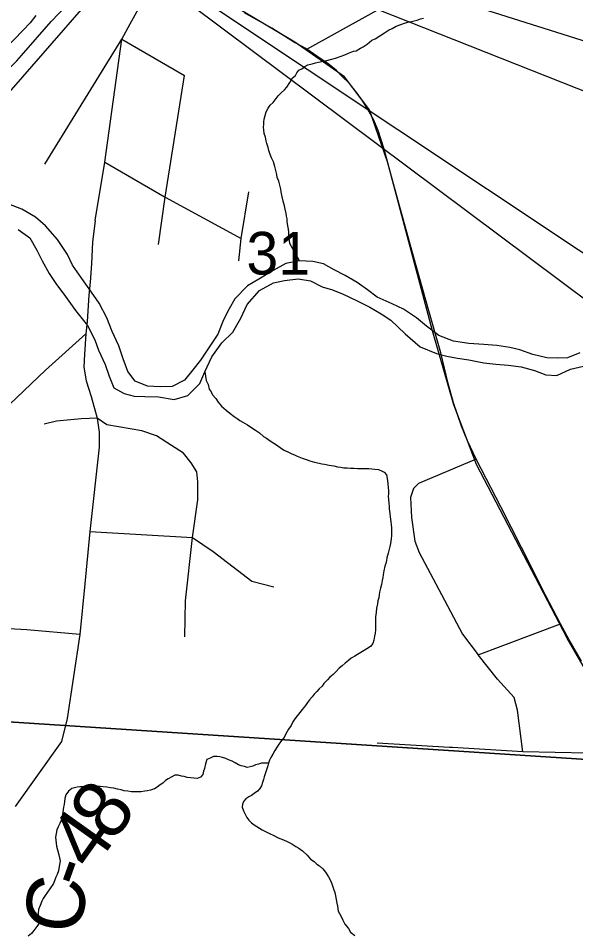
# Model space of a CAD drawing. Extents: x -7.3 to 34, y 0 to 22.
# Drawn here: x 5.85 to 6.397, y 16.795 to 17.693 of the extents above; entities that cross this region are included whole.
import ezdxf

# ---------------------------------------------------------------- set-up
doc = ezdxf.new("R2010")
doc.units = 0
for name, color, linetype in [('GM_X_City_Street', 7, 'Continuous'), ('GM_X_Corporation', 7, 'Continuous'), ('GM_X_County_Road', 7, 'Continuous'), ('GM_X_County_Road_Text', 7, 'Continuous'), ('GM_X_Minor_River', 7, 'Continuous'), ('GM_X_Rail_Line', 7, 'Continuous'), ('GM_X_Section_Text', 7, 'Continuous'), ('GM_X_State_Route', 7, 'Continuous'), ('GM_X_Township_Road', 7, 'Continuous'), ('SH_Text', 7, 'Continuous')]:
    doc.layers.add(name, color=color, linetype=linetype)

msp = doc.modelspace()

# ---------------------------------------------------------------- linework, layer by layer
at = {"layer": 'GM_X_City_Street'}
msp.add_line((5.95202, 17.6727), (6.01356, 17.63712), dxfattribs=at)
for points in [[(5.9603, 17.6877), (5.99248, 17.74606), (6.01125, 17.77956), (6.03537, 17.82356), (6.0802, 17.90362)], [(6.13346, 17.66283), (6.22348, 17.71318), (6.26156, 17.73491), (6.2753, 17.74533), (6.30856, 17.78468)], [(5.87653, 17.54988), (5.95202, 17.6727), (5.9603, 17.6877)], [(5.92595, 17.49492), (5.93516, 17.5519), (5.95202, 17.6727)], [(5.98785, 17.4714), (5.99455, 17.51771), (6.01356, 17.63712)], [(5.93516, 17.5519), (5.99455, 17.51771), (6.06913, 17.47725)], [(6.06657, 17.45507), (6.06913, 17.47725), (6.07656, 17.52294)]]:
    msp.add_lwpolyline(points, dxfattribs=at)
at = {"layer": 'GM_X_Corporation'}
for points in [[(6.6194, 17.97528), (6.52813, 16.95829), (5.47925, 17.0267), (5.53789, 17.64554), (5.56554, 17.70179), (5.57775, 17.76291), (5.58915, 17.78389), (5.62007, 17.79576), (5.64648, 17.80963), (5.68028, 17.83281), (5.71683, 17.86124), (5.75226, 17.89045), (5.78471, 17.92199), (5.81953, 17.95841), (5.83347, 17.97366), (5.84752, 17.9942), (5.85847, 18.01178), (5.86655, 18.01806)], [(6.52813, 16.95829), (6.43707, 15.95076), (5.38425, 16.01167), (5.47925, 17.0267)]]:
    msp.add_lwpolyline(points, close=True, dxfattribs=at)
at = {"layer": 'GM_X_County_Road'}
for points in [[(5.85368, 17.65674), (5.88258, 17.68992), (5.91321, 17.72206), (5.94428, 17.77432)], [(5.45148, 17.27852), (5.47147, 17.28366), (5.48207, 17.28712), (5.49092, 17.29091), (5.50286, 17.29739), (5.51335, 17.30485), (5.54486, 17.33714), (5.57923, 17.37285), (5.64874, 17.44645), (5.84908, 17.65146), (5.85368, 17.65674)], [(5.92595, 17.49492), (5.92336, 17.47358), (5.9223, 17.45236), (5.92109, 17.43417), (5.91972, 17.42159), (5.9179, 17.39566), (5.91663, 17.38366), (5.91532, 17.36352), (5.91487, 17.35079), (5.917, 17.33745), (5.92184, 17.32214), (5.92791, 17.30076), (5.92973, 17.28711), (5.92973, 17.27241), (5.92063, 17.18978), (5.91578, 17.13855), (5.91093, 17.08882), (5.89846, 17.00638), (5.89291, 16.98373), (5.84726, 16.91993)]]:
    msp.add_lwpolyline(points, dxfattribs=at)
at = {"layer": 'GM_X_Minor_River'}
for points in [[(6.12636, 17.45537), (6.11665, 17.47206), (6.11634, 17.47511), (6.11496, 17.47817), (6.11571, 17.48083), (6.11576, 17.48349), (6.11544, 17.48616), (6.11476, 17.48959), (6.11409, 17.49379), (6.11415, 17.49645), (6.11345, 17.49912), (6.11312, 17.50179), (6.11208, 17.506), (6.11139, 17.50905), (6.11035, 17.51364), (6.10965, 17.51669), (6.10896, 17.51975), (6.10827, 17.52281), (6.10795, 17.52547), (6.1069, 17.5293), (6.10585, 17.5335), (6.10441, 17.53695), (6.10409, 17.54), (6.10304, 17.54383), (6.10198, 17.54765), (6.10057, 17.55224), (6.09875, 17.55609), (6.09731, 17.55954), (6.09626, 17.56336), (6.09556, 17.56642), (6.09413, 17.57025), (6.09343, 17.57293), (6.09275, 17.57637), (6.09169, 17.58019), (6.09138, 17.58362), (6.09106, 17.58629), (6.09112, 17.58895), (6.09118, 17.59161), (6.09161, 17.59426), (6.09245, 17.59766), (6.09367, 17.60144), (6.09564, 17.60481), (6.0976, 17.60781), (6.10031, 17.61041), (6.10343, 17.61453), (6.10539, 17.61715), (6.10811, 17.62013), (6.11159, 17.62309), (6.11392, 17.62571), (6.11667, 17.63021), (6.11942, 17.63471), (6.12213, 17.63693), (6.1237, 17.63956), (6.12565, 17.64218), (6.12834, 17.64364), (6.13142, 17.64585), (6.13449, 17.64731), (6.13868, 17.64836), (6.14174, 17.64943), (6.14479, 17.65012), (6.14936, 17.65117), (6.15317, 17.65184), (6.1566, 17.65253), (6.16156, 17.65394), (6.16692, 17.65611), (6.17074, 17.65716), (6.17419, 17.65899), (6.17916, 17.66078), (6.18182, 17.66111), (6.18605, 17.66367), (6.18874, 17.66513), (6.19259, 17.66771), (6.19723, 17.67179), (6.20028, 17.67287), (6.2049, 17.67581), (6.20951, 17.67875), (6.21336, 17.68133), (6.21719, 17.68315), (6.22104, 17.68534), (6.22563, 17.68714), (6.22906, 17.68821), (6.2325, 17.68927), (6.23593, 17.68996), (6.2386, 17.69066), (6.24165, 17.69136), (6.24471, 17.69243), (6.24776, 17.69312)], [(5.94253, 17.38594), (5.93719, 17.39937), (5.9296, 17.41362), (5.9223, 17.42444), (5.91279, 17.43797), (5.90365, 17.45112), (5.89861, 17.4615), (5.88876, 17.47619), (5.87697, 17.4894), (5.86733, 17.498), (5.85389, 17.50594), (5.84112, 17.51082)], [(5.85033, 17.4859), (5.86187, 17.47763), (5.86877, 17.46568), (5.8738, 17.45529), (5.88069, 17.44296), (5.88725, 17.43292), (5.89678, 17.42014), (5.90666, 17.4066), (5.91842, 17.39187), (5.92563, 17.37763), (5.92916, 17.36766), (5.93562, 17.35344), (5.93949, 17.34195), (5.94413, 17.33082), (5.95422, 17.32524), (5.96401, 17.32234), (5.97462, 17.32207), (5.98788, 17.32173), (6.00336, 17.31906), (6.01674, 17.32328), (6.02842, 17.33476), (6.03327, 17.34642), (6.0401, 17.36106), (6.04994, 17.37487), (6.06083, 17.38523), (6.06877, 17.39908), (6.0748, 17.41223), (6.08692, 17.42598), (6.10077, 17.4336), (6.11145, 17.43599), (6.12476, 17.43755), (6.13685, 17.43573), (6.14845, 17.42974), (6.15861, 17.42682), (6.16911, 17.42238), (6.18223, 17.41635), (6.19533, 17.40994), (6.20616, 17.4032), (6.21585, 17.39688), (6.22992, 17.38361), (6.24437, 17.37071), (6.26051, 17.36422), (6.27068, 17.36169), (6.28125, 17.3599), (6.2922, 17.3581), (6.30691, 17.35507), (6.31864, 17.35401), (6.33075, 17.35295), (6.34359, 17.3511), (6.35678, 17.34773), (6.36766, 17.34328), (6.37864, 17.34262), (6.39208, 17.34912), (6.40466, 17.35184)], [(6.40121, 17.36484), (6.38896, 17.36021), (6.37946, 17.35969), (6.36885, 17.35996), (6.35491, 17.36335), (6.34213, 17.36785), (6.33234, 17.37038), (6.31987, 17.37222), (6.30701, 17.3733), (6.29224, 17.37406), (6.27713, 17.37634), (6.26287, 17.38202), (6.25059, 17.39106), (6.24094, 17.39929), (6.22828, 17.40796), (6.21704, 17.41319), (6.20241, 17.41963), (6.19274, 17.42672), (6.18268, 17.43381), (6.17111, 17.44094), (6.16026, 17.44653), (6.14979, 17.45212), (6.13924, 17.45466), (6.12636, 17.45537), (6.11264, 17.45268), (6.10033, 17.44577), (6.08646, 17.43738), (6.07529, 17.43083), (6.06282, 17.41785), (6.05725, 17.40811), (6.05166, 17.39723), (6.04599, 17.38332), (6.03769, 17.37062), (6.02902, 17.35792), (6.02156, 17.34823), (6.01334, 17.33818), (6.00142, 17.33203), (5.98966, 17.33156), (5.97716, 17.33226), (5.96515, 17.33712), (5.95782, 17.3468), (5.95321, 17.35908), (5.94899, 17.37172), (5.94253, 17.38594)], [(6.03327, 17.34642), (6.03459, 17.33785), (6.03676, 17.33387), (6.03769, 17.32933), (6.03953, 17.32663), (6.04099, 17.32394), (6.04432, 17.32007), (6.04652, 17.3166), (6.04985, 17.31272), (6.05432, 17.30883), (6.05804, 17.3057), (6.06215, 17.30257), (6.06514, 17.30061), (6.06775, 17.29865), (6.07075, 17.29706), (6.07524, 17.2943), (6.07935, 17.29155), (6.08309, 17.28919), (6.08683, 17.28645), (6.09092, 17.28294), (6.09392, 17.28135), (6.09654, 17.2794), (6.10102, 17.27626), (6.10364, 17.27468), (6.1085, 17.27115), (6.11112, 17.26958), (6.116, 17.26719), (6.11862, 17.26599), (6.12125, 17.26479), (6.12388, 17.2636), (6.12877, 17.26159), (6.13367, 17.25996), (6.1363, 17.25915), (6.14083, 17.25791), (6.14535, 17.25667), (6.148, 17.25623), (6.15064, 17.25579), (6.15518, 17.25493), (6.15971, 17.25407), (6.16348, 17.25323), (6.16651, 17.25278), (6.16953, 17.25234), (6.17295, 17.25227), (6.17635, 17.25181), (6.17938, 17.25174), (6.18317, 17.25166), (6.18621, 17.25159), (6.19076, 17.2515), (6.19417, 17.25142), (6.1972, 17.25136), (6.20023, 17.25091), (6.20363, 17.25045), (6.20664, 17.24925), (6.20927, 17.24805), (6.21148, 17.24534), (6.2125, 17.23962), (6.2128, 17.23619), (6.21311, 17.23276), (6.21342, 17.22972), (6.21335, 17.22668), (6.2133, 17.22402), (6.21362, 17.22135), (6.21391, 17.21716), (6.21423, 17.21449), (6.21417, 17.21184), (6.21483, 17.20726), (6.21514, 17.20421), (6.21579, 17.19926), (6.21611, 17.19659), (6.21642, 17.19316), (6.21634, 17.18974), (6.21626, 17.18594), (6.21619, 17.18252), (6.21533, 17.17798), (6.21489, 17.17495), (6.21407, 17.17231), (6.21323, 17.16852), (6.21199, 17.16399), (6.21156, 17.16134), (6.21073, 17.15832), (6.20992, 17.15567), (6.20906, 17.15113), (6.20822, 17.14735), (6.20778, 17.1447), (6.20734, 17.14167), (6.2065, 17.13788), (6.20565, 17.1341), (6.20481, 17.13032), (6.20438, 17.12767), (6.20393, 17.12464), (6.20311, 17.12162), (6.20267, 17.11896), (6.20181, 17.11442), (6.20134, 17.11025), (6.20087, 17.10608), (6.20082, 17.10342), (6.20075, 17.10038), (6.20065, 17.09582), (6.20059, 17.09316)], [(6.20059, 17.09316), (6.20053, 17.09012), (6.1997, 17.0871), (6.19924, 17.08331), (6.19803, 17.07992), (6.19569, 17.07693), (6.19223, 17.07472), (6.18953, 17.07288), (6.18646, 17.07105), (6.183, 17.06922), (6.18031, 17.06738), (6.17686, 17.06555), (6.17415, 17.06333), (6.17106, 17.06074), (6.16797, 17.05815), (6.16526, 17.05555), (6.16216, 17.05257), (6.15906, 17.0496), (6.15597, 17.04701), (6.15364, 17.0444), (6.15014, 17.04067), (6.14857, 17.03805), (6.14548, 17.03545), (6.14315, 17.03284), (6.14043, 17.03024), (6.13848, 17.02762), (6.13614, 17.02463), (6.13418, 17.02202), (6.13222, 17.01902), (6.12873, 17.0153), (6.12639, 17.0123), (6.12404, 17.00894), (6.1217, 17.00595), (6.11974, 17.00295), (6.11815, 16.99956), (6.11541, 16.99582), (6.11266, 16.99132), (6.11106, 16.98755), (6.10872, 16.98495), (6.10599, 16.9812), (6.10441, 16.97858), (6.10206, 16.97483), (6.10009, 16.97145), (6.09812, 16.96807), (6.09692, 16.96544), (6.09572, 16.96243), (6.09528, 16.95977), (6.09366, 16.95487), (6.09246, 16.95223), (6.09164, 16.94921), (6.09082, 16.94657), (6.09, 16.94355), (6.08879, 16.94015), (6.08721, 16.93753), (6.08488, 16.93492), (6.0818, 16.9327), (6.0791, 16.93086), (6.07641, 16.9294), (6.07372, 16.92756), (6.07139, 16.92495), (6.07019, 16.92232), (6.07013, 16.91928), (6.07119, 16.91583), (6.07265, 16.91314), (6.07446, 16.9093), (6.07668, 16.90659), (6.07927, 16.90387), (6.08189, 16.90192), (6.08451, 16.90034), (6.08713, 16.89877), (6.08975, 16.89719), (6.09275, 16.8956), (6.09688, 16.89361), (6.10101, 16.89162), (6.10513, 16.88925), (6.10776, 16.88843), (6.11039, 16.88723), (6.11415, 16.88563), (6.11865, 16.88326), (6.12277, 16.88088), (6.12539, 16.87931), (6.12913, 16.87657), (6.13359, 16.87229), (6.13692, 16.86841), (6.14066, 16.86605), (6.14325, 16.86334), (6.14587, 16.86176), (6.14923, 16.85903), (6.15181, 16.85555), (6.15474, 16.85093), (6.15693, 16.8467), (6.15837, 16.84325), (6.15942, 16.83942), (6.16086, 16.83559), (6.16155, 16.83254), (6.16222, 16.82872), (6.16291, 16.82528), (6.1636, 16.82223), (6.16425, 16.81727), (6.16681, 16.81266), (6.16861, 16.80844)], [(6.09572, 16.96243), (6.08889, 16.96257), (6.08584, 16.9615), (6.08317, 16.9608), (6.08049, 16.95972), (6.07782, 16.95902), (6.07477, 16.95832), (6.07213, 16.95914), (6.06911, 16.95997), (6.06648, 16.96078), (6.06311, 16.96276), (6.06011, 16.96434), (6.05673, 16.96594), (6.0541, 16.96713), (6.0507, 16.96797), (6.04807, 16.96879), (6.04542, 16.96922), (6.042, 16.96892), (6.03855, 16.96747), (6.03549, 16.96602), (6.03388, 16.96187), (6.03302, 16.95733), (6.03221, 16.95469), (6.03138, 16.95128), (6.02904, 16.94868), (6.02599, 16.9476), (6.02257, 16.94768), (6.01955, 16.94812), (6.01615, 16.94858), (6.01313, 16.9494), (6.01048, 16.94984), (6.00709, 16.95067), (6.00405, 16.95074), (6.00099, 16.94929), (5.99753, 16.94708), (5.99484, 16.94562), (5.99213, 16.94302), (5.98943, 16.94118), (5.98673, 16.93896), (5.98404, 16.93749), (5.98022, 16.93606), (5.97717, 16.93536), (5.97451, 16.93504), (5.97108, 16.93436), (5.96729, 16.93444), (5.96425, 16.9345), (5.9616, 16.93456), (5.95782, 16.93503), (5.95441, 16.93548), (5.9514, 16.9363), (5.94762, 16.93715), (5.94423, 16.93798), (5.94082, 16.93844), (5.93742, 16.93889), (5.93364, 16.93935), (5.93061, 16.9398), (5.9272, 16.93987), (5.92454, 16.93993), (5.92075, 16.93963), (5.91733, 16.93971), (5.91391, 16.9394), (5.91088, 16.93947), (5.90822, 16.93915), (5.90555, 16.93845), (5.90288, 16.93774), (5.89979, 16.93515), (5.89705, 16.93141), (5.89622, 16.92801), (5.89577, 16.92498), (5.89533, 16.92194), (5.89489, 16.91929), (5.89402, 16.91437), (5.89355, 16.9102), (5.89233, 16.90643), (5.89113, 16.90341), (5.88954, 16.90003), (5.88834, 16.89701), (5.8875, 16.89361), (5.88704, 16.88982), (5.88736, 16.88715), (5.88768, 16.88411), (5.88799, 16.88106), (5.88905, 16.87762), (5.89008, 16.87265), (5.89078, 16.8696), (5.89147, 16.86654), (5.89101, 16.86313), (5.88974, 16.85708), (5.88852, 16.8533), (5.88733, 16.85067), (5.88613, 16.84804), (5.88492, 16.84464), (5.88139, 16.8394), (5.87904, 16.83603), (5.87669, 16.83266), (5.87473, 16.82966), (5.87354, 16.82703), (5.87193, 16.82288), (5.87033, 16.81912)], [(5.87033, 16.81912), (5.86986, 16.81495), (5.87017, 16.8119), (5.8705, 16.80923), (5.87119, 16.80618), (5.86961, 16.80355), (5.86766, 16.80093), (5.86571, 16.79832), (5.86337, 16.79533), (5.86028, 16.79273)], [(6.16861, 16.80844), (6.1708, 16.80459), (6.17412, 16.80034), (6.17633, 16.79687), (6.18042, 16.79336)]]:
    msp.add_lwpolyline(points, dxfattribs=at)
at = {"layer": 'GM_X_Rail_Line'}
for points in [[(4.45231, 17.19119), (4.48538, 17.20432), (4.60552, 17.25733), (4.67674, 17.28373), (4.73716, 17.30516), (4.78626, 17.31272), (4.82407, 17.31644), (4.85321, 17.31341), (4.89606, 17.2953), (4.95783, 17.26522), (5.03164, 17.2283), (5.13232, 17.17415), (5.20356, 17.13808), (5.25623, 17.12574), (5.30545, 17.12026), (5.35857, 17.13059), (5.40047, 17.15081), (5.45338, 17.18284), (5.47692, 17.20296), (5.51417, 17.24265), (5.56302, 17.30268), (5.71283, 17.4728), (5.91469, 17.70431), (5.95678, 17.76785)], [(8.11709, 14.1), (7.76999, 14.70077), (7.42724, 15.29301), (6.5394, 16.82455), (6.38864, 17.08509), (6.29961, 17.25554), (6.27749, 17.31385), (6.25668, 17.38643), (6.21296, 17.55142), (6.19485, 17.60347), (6.17034, 17.63582), (6.12175, 17.66972), (5.95678, 17.76785)], [(5.86779, 17.69587), (5.86218, 17.68852), (5.85518, 17.68133), (5.83659, 17.66207)]]:
    msp.add_lwpolyline(points, dxfattribs=at)
at = {"layer": 'GM_X_State_Route'}
for points in [[(6.13253, 17.66333), (6.12128, 17.66929), (6.09898, 17.68354), (6.074, 17.69744), (6.07233, 17.69847)], [(6.40264, 17.06264), (6.39069, 17.08356), (6.38217, 17.09911), (6.3678, 17.12673), (6.34405, 17.174), (6.32369, 17.21402), (6.29942, 17.26065), (6.29102, 17.27863), (6.28505, 17.29313), (6.27737, 17.31592), (6.27189, 17.33492), (6.26482, 17.3649), (6.25288, 17.40633), (6.23838, 17.45848), (6.22388, 17.51052), (6.2145, 17.545), (6.20926, 17.56462), (6.20329, 17.58289), (6.1989, 17.59374), (6.19329, 17.60373), (6.18842, 17.61171), (6.18245, 17.62), (6.17508, 17.62902), (6.16746, 17.63669), (6.16241, 17.64175), (6.15399, 17.64876), (6.14662, 17.65382), (6.13346, 17.66283), (6.13253, 17.66333)]]:
    msp.add_lwpolyline(points, dxfattribs=at)
at = {"layer": 'GM_X_Township_Road'}
for p, q in [((6.29942, 17.26065), (6.24289, 17.23689)), ((6.27335, 16.97801), (6.20231, 16.98222))]:
    msp.add_line(p, q, dxfattribs=at)
for points in [[(5.91093, 17.08882), (5.85878, 17.09337), (5.83543, 17.09458), (5.80026, 17.12763), (5.79617, 17.13642), (5.79602, 17.1437), (5.80291, 17.22722), (5.80663, 17.26816), (5.80905, 17.27711), (5.81663, 17.28818), (5.8418, 17.31441), (5.87697, 17.34791), (5.91663, 17.38366)], [(5.92791, 17.30076), (5.91214, 17.30015), (5.90198, 17.29939), (5.88804, 17.29803), (5.87591, 17.29515)], [(6.01372, 17.08639), (6.01432, 17.12187), (6.0213, 17.18402), (6.02645, 17.22086), (6.0266, 17.23845), (6.02539, 17.2483), (6.02008, 17.25725), (6.01235, 17.2665), (6.00068, 17.27423), (5.98582, 17.28347), (5.97172, 17.28833), (5.93716, 17.29424), (5.92791, 17.30076)], [(6.24289, 17.23689), (6.23801, 17.23189), (6.23504, 17.22318), (6.23594, 17.2035), (6.23936, 17.18011), (6.24349, 17.16902), (6.26543, 17.12796), (6.28615, 17.08921), (6.30126, 17.06873)], [(5.92063, 17.18978), (6.0213, 17.18402), (6.04146, 17.17023), (6.07951, 17.14097), (6.10104, 17.13551)], [(6.34512, 16.97369), (6.34001, 17.01463), (6.33684, 17.02682), (6.32051, 17.04485), (6.30126, 17.06873), (6.38217, 17.09911)], [(6.44499, 16.9894), (6.42165, 16.97588), (6.40849, 16.97247), (6.34512, 16.97369), (6.2764, 16.97783), (6.27335, 16.97801)]]:
    msp.add_lwpolyline(points, dxfattribs=at)
at = {"layer": 'SH_Text'}
for points in [[(9.4026, 16.43559), (9.40269, 16.72504), (5.79469, 17.86363)], [(9.4026, 15.17784), (9.40269, 15.46729), (5.86898, 17.81942)]]:
    msp.add_lwpolyline(points, close=True, dxfattribs=at)

# ---------------------------------------------------------------- texts
at = {"layer": 'GM_X_County_Road_Text'}
for s, rotation, p in [('8', 54.31047, (5.94308, 16.88367)), ('4', 54.51857, (5.92279, 16.85521)), ('-', 70.25899, (5.91682, 16.8369)), ('C', 82.94952, (5.91186, 16.79381))]:
    msp.add_text(s, height=0.05682, rotation=rotation, dxfattribs=at).set_placement(p)
at = {"layer": 'GM_X_Section_Text'}
msp.add_text('31', height=0.041856, rotation=0.00001, dxfattribs=at).set_placement((6.0742, 17.44178))

doc.saveas('drawing.dxf')
